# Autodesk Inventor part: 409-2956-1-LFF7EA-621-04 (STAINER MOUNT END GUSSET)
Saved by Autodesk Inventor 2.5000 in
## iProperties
Created: 2010-06
Part Number: 409-2956-1-LFF7EA-621-04 (STAINER MOUNT END GUSSET)
Cost Center: 0 lbmass
Material: A36 STEEL PLATE
Document SubType Name: Sheet Metal
Designer: S. Boerckel
Authority: 0 in^3
Mass: 784.889 g
Surface Area: 258.236 cm^2
Volume: 99.8587 cm^3
Density: 7.86 g/cm^3
Flat Pattern Width: 6.35 cm
Flat Pattern Length: 22.86 cm
Flat Pattern Area: 145.161 cm^2
Sheet Metal Rule: 3/8"Thk
Sheet Metal Width: 9.0000 in
Sheet Metal Length: 22.5000 in^2
Description: STRAINER MOUNT END GUSSET
User Status: BURN
SaveDate: 2008-01-15
SaveTime: 10:24
FileName: Sheet Metal
Wide: =<Flat Pattern Width>cm
Length: =<Flat Pattern Length>cm
Thickness: 0.3750 in
SMR: =<Sheet Metal Rule> - <Material>
Author: S. Boerckel
Revision Number: 0
Subject: DEMIN WATER FORWARDING PUMP SKID-7EA
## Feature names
1. Plate1
